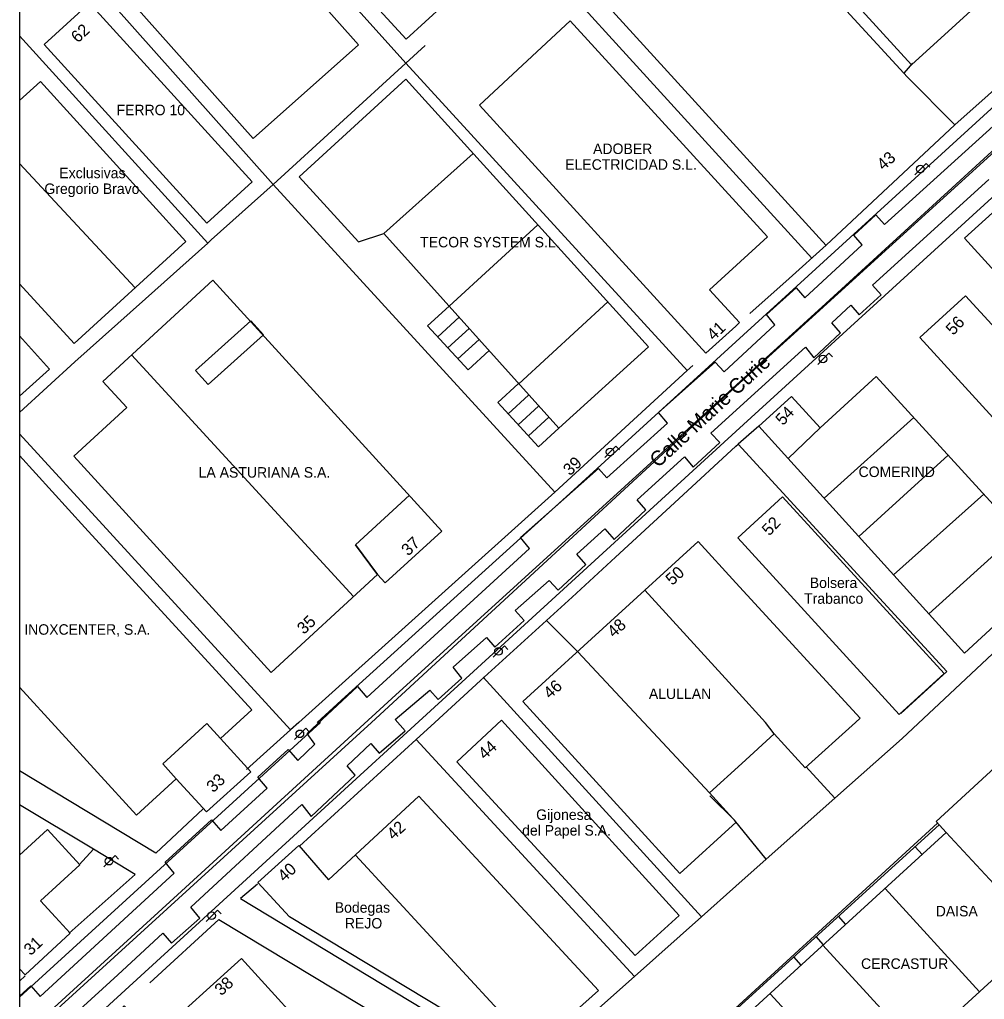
# Model space of a CAD drawing. Extents: x 282771 to 285132, y 4823109 to 4825496.
# Drawn here: x 282771.5 to 282932.6, y 4823249.3 to 4823412.9 of the extents above; entities that cross this region are included whole.
import ezdxf

# ---------------------------------------------------------------- set-up
doc = ezdxf.new("R2010")
doc.units = 0
for name, color, linetype in [('ACERA-BORDILLO', 7, 'Continuous'), ('ACERA-INTERIOR', 7, 'Continuous'), ('APARCAMIENTO', 7, 'Continuous'), ('CALLE-EJE', 7, 'Continuous'), ('CALLE-TEXTO', 7, 'Continuous'), ('Default', 7, 'Continuous'), ('EDIFICIO', 7, 'Continuous'), ('FAROLA', 7, 'Continuous'), ('MEDIANERA', 7, 'Continuous'), ('NUM-LOCAL', 7, 'Continuous'), ('SENAL-VIARIA', 7, 'Continuous'), ('TXT-EMPRESAS', 7, 'Continuous'), ('VALLA', 7, 'Continuous')]:
    doc.layers.add(name, color=color, linetype=linetype)

msp = doc.modelspace()

# ---------------------------------------------------------------- linework, layer by layer
at = {"layer": 'ACERA-BORDILLO'}
for points in [[(283029.13, 4823485.09), (282891.09, 4823359.12), (282862.13, 4823332.68), (282825.85, 4823299.82), (282821.21, 4823295.56), (282825.85, 4823299.82)], [(282771.5, 4823234.68), (282891.09, 4823344.12), (283036.58, 4823476.99)], [(282821.74, 4823295.56), (282771.5, 4823249.66)]]:
    msp.add_lwpolyline(points, dxfattribs=at)
at = {"layer": 'ACERA-INTERIOR'}
for points in [[(282927.64, 4823395.32), (282906.15, 4823375.22), (282899.98, 4823369.7), (282893.44, 4823363.85)], [(282883.88, 4823355.13), (282882.97, 4823354.3), (282860.87, 4823334.01)], [(282894.91, 4823345.04), (282893.25, 4823343.57), (282891.46, 4823342)], [(282837.71, 4823292.69), (282840.85, 4823295.56), (282848.48, 4823302.52), (282859.47, 4823312.55), (282863.76, 4823316.46), (282870.99, 4823323.12), (282881.56, 4823332.87), (282891.09, 4823341.65), (282891.46, 4823342)], [(282918.62, 4823297.05), (282926.32, 4823304.05), (282891.46, 4823342)], [(282772.44, 4823253.22), (282771.5, 4823252.36)]]:
    msp.add_lwpolyline(points, dxfattribs=at)
at = {"layer": 'APARCAMIENTO'}
for points in [[(282849.9, 4823357.63), (282846.38, 4823354.4), (282839.62, 4823361.78), (282843.23, 4823365.05)], [(282841.31, 4823359.93), (282844.88, 4823363.21)], [(282843, 4823358.09), (282846.56, 4823361.35)], [(282844.69, 4823356.24), (282848.23, 4823359.49)], [(282854.77, 4823352.06), (282851.37, 4823348.94), (282858.13, 4823341.57), (282861.53, 4823344.69)], [(282853.07, 4823347.1), (282856.46, 4823350.22)], [(282854.76, 4823345.26), (282858.15, 4823348.37)], [(282856.45, 4823343.42), (282859.84, 4823346.53)], [(282924.78, 4823278.75), (282885.66, 4823242.92), (282885.14, 4823242.26), (282884.67, 4823241.57), (282884.26, 4823240.85), (282883.9, 4823240.09), (282883.61, 4823239.31), (282883.37, 4823238.51), (282883.2, 4823237.7), (282883.09, 4823236.87), (282883.05, 4823236.04), (282883.06, 4823235.62), (282883.07, 4823235.2), (282883.16, 4823234.38), (282883.36, 4823234.18)], [(282925.04, 4823278.45), (282886.53, 4823243.44), (282887.75, 4823241.95)], [(282922.22, 4823273.52), (282921.01, 4823274.78)], [(282909.45, 4823261.82), (282908.25, 4823263.18)], [(282905.73, 4823258.42), (282904.5, 4823259.78)], [(282901.99, 4823254.99), (282900.77, 4823256.39)]]:
    msp.add_lwpolyline(points, dxfattribs=at)
at = {"layer": 'CALLE-EJE'}
msp.add_lwpolyline([(282771.5, 4823241.96), (282830.25, 4823295.56), (282891.09, 4823351.62), (283043.73, 4823490.38)], dxfattribs=at)
at = {"layer": 'Default'}
msp.add_lwpolyline([(285130.1, 4825495.5), (282771.5, 4825495.5), (282771.5, 4823109)], dxfattribs=at)
at = {"layer": 'EDIFICIO'}
for points in [[(282912.81, 4823473.09), (282950.02, 4823432.35), (282920.44, 4823405.34), (282883.23, 4823446.08), (282912.81, 4823473.09)], [(282818.89, 4823428.36), (282835.44, 4823443.52), (282852.61, 4823424.78), (282851.88, 4823424.16), (282836.06, 4823409.62), (282818.89, 4823428.36)], [(282805.51, 4823434.11), (282785.84, 4823420.77), (282810.49, 4823393.05), (282828.1, 4823408.7), (282805.51, 4823434.11)], [(282810.34, 4823385.81), (282802.77, 4823378.92), (282775.61, 4823408.74), (282783.18, 4823415.63), (282810.34, 4823385.81)], [(282886.69, 4823367.79), (282891.7, 4823362.3), (282891.09, 4823361.71), (282886.1, 4823357.19), (282848.28, 4823398.63), (282863.4, 4823412.68), (282896.35, 4823376.62), (282886.69, 4823367.79)], [(282771.5, 4823399.42), (282775, 4823402.59), (282799.28, 4823375.87), (282780.61, 4823358.82), (282771.5, 4823368.8)], [(282861.53, 4823344.69), (282876.5, 4823358.27), (282835.98, 4823402.95), (282818.2, 4823386.64), (282828.09, 4823375.82), (282832.34, 4823377.16), (282861.53, 4823344.69)], [(282985.15, 4823353.84), (282980.04, 4823359.45), (282978.44, 4823357.99), (282951.98, 4823386.98), (282940.16, 4823376.19), (282935.13, 4823381.68), (282929.25, 4823376.4), (282960.81, 4823341.73), (282957.9, 4823339.08), (282962.88, 4823333.6), (282985.15, 4823353.84)], [(282803.77, 4823369.38), (282842.01, 4823327.5), (282832.52, 4823318.83), (282831.24, 4823320.22), (282813.53, 4823303.91), (282780.54, 4823340.03), (282789.4, 4823348.12), (282785.41, 4823352.48), (282803.77, 4823369.38)], [(282956.38, 4823337.43), (282929.45, 4823366.8), (282921.79, 4823359.8), (282948.55, 4823330.48), (282956.21, 4823337.48)], [(282771.5, 4823360.08), (282776.51, 4823354.53), (282771.5, 4823350)], [(282929.26, 4823307.1), (282894.91, 4823345.04), (282900.36, 4823349.97), (282905.14, 4823344.75), (282914.53, 4823353.32), (282944.18, 4823320.84), (282929.26, 4823307.1)], [(282771.5, 4823340.1), (282782.4, 4823328.07), (282810.27, 4823297.65), (282807.65, 4823295.26), (282805.02, 4823292.86), (282810.08, 4823287.3), (282802.71, 4823280.59), (282797.65, 4823286.14), (282791.01, 4823280.08), (282771.5, 4823301.46)], [(282925.86, 4823303.74), (282918.38, 4823296.89), (282891.4, 4823326.37), (282898.88, 4823333.22), (282925.86, 4823303.74)], [(282911.84, 4823296.23), (282911.08, 4823295.56), (282902.68, 4823287.94), (282897.48, 4823293.64), (282892.08, 4823288.71), (282886.68, 4823283.77), (282891.14, 4823278.89), (282881.72, 4823270.3), (282855.52, 4823299.03), (282884.79, 4823325.76), (282891.09, 4823318.88), (282911.84, 4823296.23)], [(282851.95, 4823295.91), (282881.63, 4823263.33), (282874.25, 4823256.6), (282844.52, 4823288.95), (282851.95, 4823295.91)], [(282926.22, 4823277.18), (282924.54, 4823279.01), (282936.46, 4823289.96), (282954.65, 4823270.16), (282947.43, 4823263.6), (282946.78, 4823264.31), (282921.44, 4823241.11), (282912.61, 4823233.03), (282903.53, 4823224.72), (282895.64, 4823233.33), (282887.75, 4823241.95), (282891.09, 4823245.03), (282926.22, 4823277.18)], [(282868.15, 4823250.78), (282855.58, 4823239.52), (282816.56, 4823263.08), (282811.29, 4823268.84), (282818.1, 4823275), (282823.05, 4823269.28), (282838.15, 4823283.21), (282868.15, 4823250.78)], [(282776.18, 4823277.66), (282781.56, 4823271.78), (282774.99, 4823265.77), (282777.47, 4823263.05), (282779.95, 4823260.33), (282772.45, 4823253.4), (282771.5, 4823254.41)], [(282771.5, 4823273.37), (282776.18, 4823277.66)], [(282783.15, 4823242.92), (282788.97, 4823248.25), (282793.93, 4823242.86), (282808.53, 4823256.11), (282836.26, 4823225.63), (282821.05, 4823211.63), (282805.83, 4823197.64), (282777.96, 4823228.22), (282788.04, 4823237.41), (282783.15, 4823242.92)]]:
    msp.add_lwpolyline(points, dxfattribs=at)
at = {"layer": 'FAROLA'}
for p, q in [((282922.86, 4823388.88), (282921.92, 4823387.95)), ((282923.45, 4823388.29), (282922.86, 4823388.88)), ((282921.92, 4823387.95), (282920.99, 4823387.01)), ((282905.68, 4823356.25), (282904.75, 4823355.31)), ((282906.62, 4823357.18), (282905.68, 4823356.25)), ((282907.21, 4823356.59), (282906.62, 4823357.18)), ((282871.07, 4823341.65), (282870.13, 4823340.72)), ((282871.66, 4823341.06), (282871.07, 4823341.65)), ((282870.13, 4823340.72), (282869.2, 4823339.78)), ((282851.5, 4823307.4), (282850.57, 4823306.46)), ((282852.44, 4823308.33), (282851.5, 4823307.4)), ((282853.03, 4823307.74), (282852.44, 4823308.33)), ((282819.27, 4823294.57), (282818.33, 4823293.64)), ((282819.86, 4823293.98), (282819.27, 4823294.57)), ((282818.33, 4823293.64), (282817.4, 4823292.7)), ((282787.43, 4823273.31), (282786.49, 4823272.38)), ((282788.02, 4823272.72), (282787.43, 4823273.31)), ((282786.49, 4823272.38), (282785.56, 4823271.44)), ((282803.6, 4823263.27), (282802.67, 4823262.33)), ((282804.54, 4823264.2), (282803.6, 4823263.27)), ((282805.13, 4823263.61), (282804.54, 4823264.2))]:
    msp.add_line(p, q, dxfattribs=at)
for centre in [(282921.88, 4823387.95), (282905.64, 4823356.25), (282870.09, 4823340.72), (282851.46, 4823307.4), (282818.29, 4823293.64), (282786.45, 4823272.38), (282803.56, 4823263.27)]:
    msp.add_circle(centre, 0.637, dxfattribs=at)
at = {"layer": 'MEDIANERA'}
for points in [[(282832.34, 4823377.16), (282847.23, 4823390.55)], [(282771.5, 4823388.86), (282790.81, 4823368.13)], [(282843.23, 4823365.05), (282858.03, 4823378.64)], [(282854.86, 4823352.11), (282869.72, 4823365.75)], [(282800.87, 4823354.32), (282810.1, 4823362.63), (282812.21, 4823360.29), (282802.98, 4823351.98), (282800.87, 4823354.32)], [(282790.19, 4823356.95), (282827.27, 4823316.57)], [(282920.79, 4823346.47), (282905.81, 4823333.02)], [(282899.83, 4823339.63), (282905.14, 4823344.75)], [(282926.51, 4823340.2), (282911.61, 4823326.61)], [(282836.59, 4823333.5), (282827.59, 4823325.18), (282836.59, 4823333.5)], [(282932.5, 4823333.64), (282917.43, 4823320.17)], [(282938.32, 4823327.26), (282923.29, 4823313.7)], [(282827.59, 4823325.18), (282831.24, 4823320.22), (282827.59, 4823325.18)], [(282875.91, 4823317.62), (282891.09, 4823300.97)], [(282864.7, 4823307.36), (282886.68, 4823283.77)], [(282897.48, 4823293.64), (282896.02, 4823295.56), (282891.09, 4823300.97)], [(282805.02, 4823292.86), (282802.76, 4823295.34), (282795.39, 4823288.62), (282797.65, 4823286.14)], [(282942.12, 4823260.04), (282934.17, 4823268.61), (282926.22, 4823277.18)], [(282827.56, 4823273.4), (282857.35, 4823241.11)], [(282915.99, 4823267.81), (282931.76, 4823250.57)], [(282905.63, 4823258.33), (282921.44, 4823241.11)], [(282896.81, 4823250.25), (282912.61, 4823233.03)]]:
    msp.add_lwpolyline(points, dxfattribs=at)
at = {"layer": 'SENAL-VIARIA'}
for points in [[(283034.57, 4823483.03), (283006.79, 4823457.82), (282977.46, 4823430.88), (282941.74, 4823398.13), (282906.1, 4823365.51), (282868.84, 4823331.54), (282833.67, 4823299.55), (282797.84, 4823266.73), (282771.5, 4823242.65)], [(282771.5, 4823249.86), (282773.39, 4823251.58), (282774.91, 4823249.8), (282797.3, 4823270.4), (282795.81, 4823272.19), (282803.55, 4823279.3), (282805.1, 4823277.48), (282812.81, 4823284.56), (282811.29, 4823286.41), (282816.35, 4823291.01), (282817.97, 4823289.19), (282820.81, 4823291.9), (282819.49, 4823293.72), (282827.93, 4823301.52), (282829.48, 4823299.71), (282856.63, 4823324.58), (282855.14, 4823326.4), (282868.18, 4823337.97), (282869.56, 4823336.38), (282879.68, 4823345.54), (282878.16, 4823347.3), (282887.62, 4823355.73), (282889.11, 4823354.11), (282897.61, 4823361.95), (282896.22, 4823363.64), (282901.15, 4823368.13), (282902.6, 4823366.45), (282912.16, 4823375.28), (282910.81, 4823376.9), (282914.44, 4823380.3), (282915.9, 4823378.68), (282939.32, 4823399.88)], [(282775.18, 4823241.78), (282787.88, 4823253.42), (282795.39, 4823260.33), (282796.84, 4823258.68), (282801.57, 4823262.88), (282800.08, 4823264.7), (282818.61, 4823281.83), (282820.16, 4823279.81), (282827.5, 4823286.76), (282826.21, 4823288.31), (282830.15, 4823292.05), (282831.54, 4823290.39), (282835.87, 4823294.16), (282834.22, 4823296.05), (282840, 4823300.94), (282841.36, 4823299.36), (282845.33, 4823302.96), (282843.87, 4823304.75), (282849.43, 4823309.74), (282850.85, 4823308.09), (282855.75, 4823312.55), (282854.22, 4823314.24), (282859.91, 4823319.23), (282861.43, 4823317.61), (282866.03, 4823321.91), (282864.54, 4823323.63), (282869.21, 4823327.9), (282870.79, 4823326.08), (282876.05, 4823331.07), (282874.63, 4823332.69), (282882.5, 4823339.87), (282883.96, 4823338.15), (282888.42, 4823342.28), (282886.93, 4823343.87), (282902.71, 4823358.23), (282904.13, 4823356.41), (282908.56, 4823360.61), (282907.14, 4823362.29), (282910.28, 4823365.2), (282911.67, 4823363.58), (282915.34, 4823366.92), (282913.92, 4823368.58), (282933.34, 4823386.21)]]:
    msp.add_lwpolyline(points, dxfattribs=at)
at = {"layer": 'VALLA'}
for points in [[(282835.99, 4823405.61), (282804.51, 4823440.68), (282816.96, 4823448), (282828.79, 4823454.96), (282856.67, 4823424.79)], [(282919.16, 4823403.94), (282891.09, 4823434.5), (282881.77, 4823444.67)], [(282858.98, 4823427.01), (282906.15, 4823375.21)], [(282903.77, 4823373.08), (282856.67, 4823424.79)], [(282780.79, 4823422.56), (282813.86, 4823385.35)], [(282802.91, 4823375.56), (282771.5, 4823410.19)], [(282835.99, 4823405.61), (282839.2, 4823408.59)], [(282943.82, 4823409.77), (282927.64, 4823395.32), (282919.7, 4823403.36), (282919.16, 4823403.94)], [(282835.99, 4823405.61), (282813.86, 4823385.35)], [(282883, 4823354.27), (282835.99, 4823405.61)], [(282920.6, 4823405.61), (282919.16, 4823403.94)], [(282813.86, 4823385.35), (282803.51, 4823376.11), (282802.91, 4823375.56)], [(282813.86, 4823385.35), (282860.87, 4823334.01), (282818.13, 4823295.56), (282816.73, 4823294.3)], [(282771.5, 4823347.28), (282780.75, 4823355.77), (282792.52, 4823366.29), (282802.91, 4823375.56)], [(282816.73, 4823294.3), (282771.5, 4823343.73)], [(282962.65, 4823333.88), (282953.74, 4823325.36), (282949.85, 4823321.91), (282918.84, 4823292.87), (282907.61, 4823282.89)], [(282859.47, 4823312.55), (282864.7, 4823307.36)], [(282885.34, 4823263.1), (282848.88, 4823303.12)], [(282809.39, 4823287.69), (282816.73, 4823294.3)], [(282818.22, 4823274.9), (282837.71, 4823292.69), (282874.14, 4823253.14)], [(282802.13, 4823281.1), (282794.26, 4823273.71), (282771.5, 4823287.48)], [(282907.61, 4823282.89), (282902.78, 4823288.17)], [(282896.17, 4823272.72), (282890.88, 4823279.2), (282886.77, 4823283.29)], [(282907.61, 4823282.89), (282896.17, 4823272.72)], [(282783.83, 4823274.37), (282771.5, 4823281.77)], [(282779.77, 4823260.34), (282790.81, 4823270.17), (282783.83, 4823274.37)], [(282781.47, 4823271.74), (282783.82, 4823274.36)], [(282885.34, 4823263.1), (282891.09, 4823268.2), (282896.17, 4823272.72)], [(282811.24, 4823268.52), (282808.38, 4823266.16), (282855.71, 4823237.53), (282856.26, 4823237.21), (282874.14, 4823253.14)], [(282885.34, 4823263.1), (282874.14, 4823253.14)], [(282793.26, 4823252.08), (282804.74, 4823262.62), (282851.83, 4823234.25), (282852.99, 4823233.55)]]:
    msp.add_lwpolyline(points, dxfattribs=at)

# ---------------------------------------------------------------- texts
at = {"layer": 'CALLE-TEXTO'}
msp.add_text('Calle Marie Curie', height=2.5, rotation=42.6586, dxfattribs=at).set_placement((282878.1, 4823337.95))
at = {"layer": 'NUM-LOCAL'}
for s, rotation, p in [('62', 43.045, (282781.22, 4823408.9)), ('43', 41.7603, (282915.72, 4823387.61)), ('56', 46.5482, (282927.38, 4823360.08)), ('41', 43.2328, (282887.38, 4823359.2)), ('54', 46.5482, (282898.94, 4823345.01)), ('39', 43.2328, (282863.38, 4823336.63)), ('52', 46.5482, (282896.67, 4823326.58)), ('37', 43.2328, (282836.37, 4823323.23)), ('50', 42.1835, (282880.46, 4823318.32)), ('35', 43.2328, (282818.96, 4823310.14)), ('48', 42.1835, (282870.72, 4823309.6)), ('46', 42.1835, (282860.06, 4823299.37)), ('44', 42.1835, (282849.17, 4823289.23)), ('33', 43.2328, (282803.83, 4823283.71)), ('42', 42.1835, (282833.92, 4823275.8)), ('40', 42.1835, (282815.69, 4823268.81)), ('31', 43.2328, (282773.33, 4823256.5)), ('38', 42.1835, (282805.17, 4823249.8))]:
    msp.add_text(s, height=2, rotation=rotation, dxfattribs=at).set_placement(p)
at = {"layer": 'TXT-EMPRESAS'}
for s, p in [('FERRO 10', (282787.68, 4823396.94)), ('ADOBER ', (282867.25, 4823390.46)), ('ELECTRICIDAD S.L.', (282862.59, 4823387.83)), ('Exclusivas ', (282778.13, 4823386.42)), ('Gregorio Bravo', (282775.64, 4823383.79)), ('TECOR SYSTEM S.L.', (282838.38, 4823374.87)), ('LA ASTURIANA S.A.', (282801.39, 4823336.42)), ('COMERIND', (282911.58, 4823336.52)), ('Bolsera ', (282903.43, 4823317.99)), ('Trabanco', (282902.48, 4823315.36)), ('INOXCENTER, S.A.', (282772.28, 4823310.19)), ('ALULLAN', (282876.57, 4823299.46)), ('Gijonesa ', (282857.74, 4823279.27)), ('del Papel S.A.', (282855.4, 4823276.65)), ('Bodegas ', (282824.12, 4823263.77)), ('DAISA', (282924.46, 4823263.16)), ('REJO', (282825.81, 4823261.14)), ('CERCASTUR', (282911.99, 4823254.39))]:
    msp.add_text(s, height=1.75, dxfattribs=at).set_placement(p)

doc.saveas('drawing.dxf')
